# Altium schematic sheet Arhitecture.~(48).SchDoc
size A3; SheetNumber: 1; SheetTotal: 2
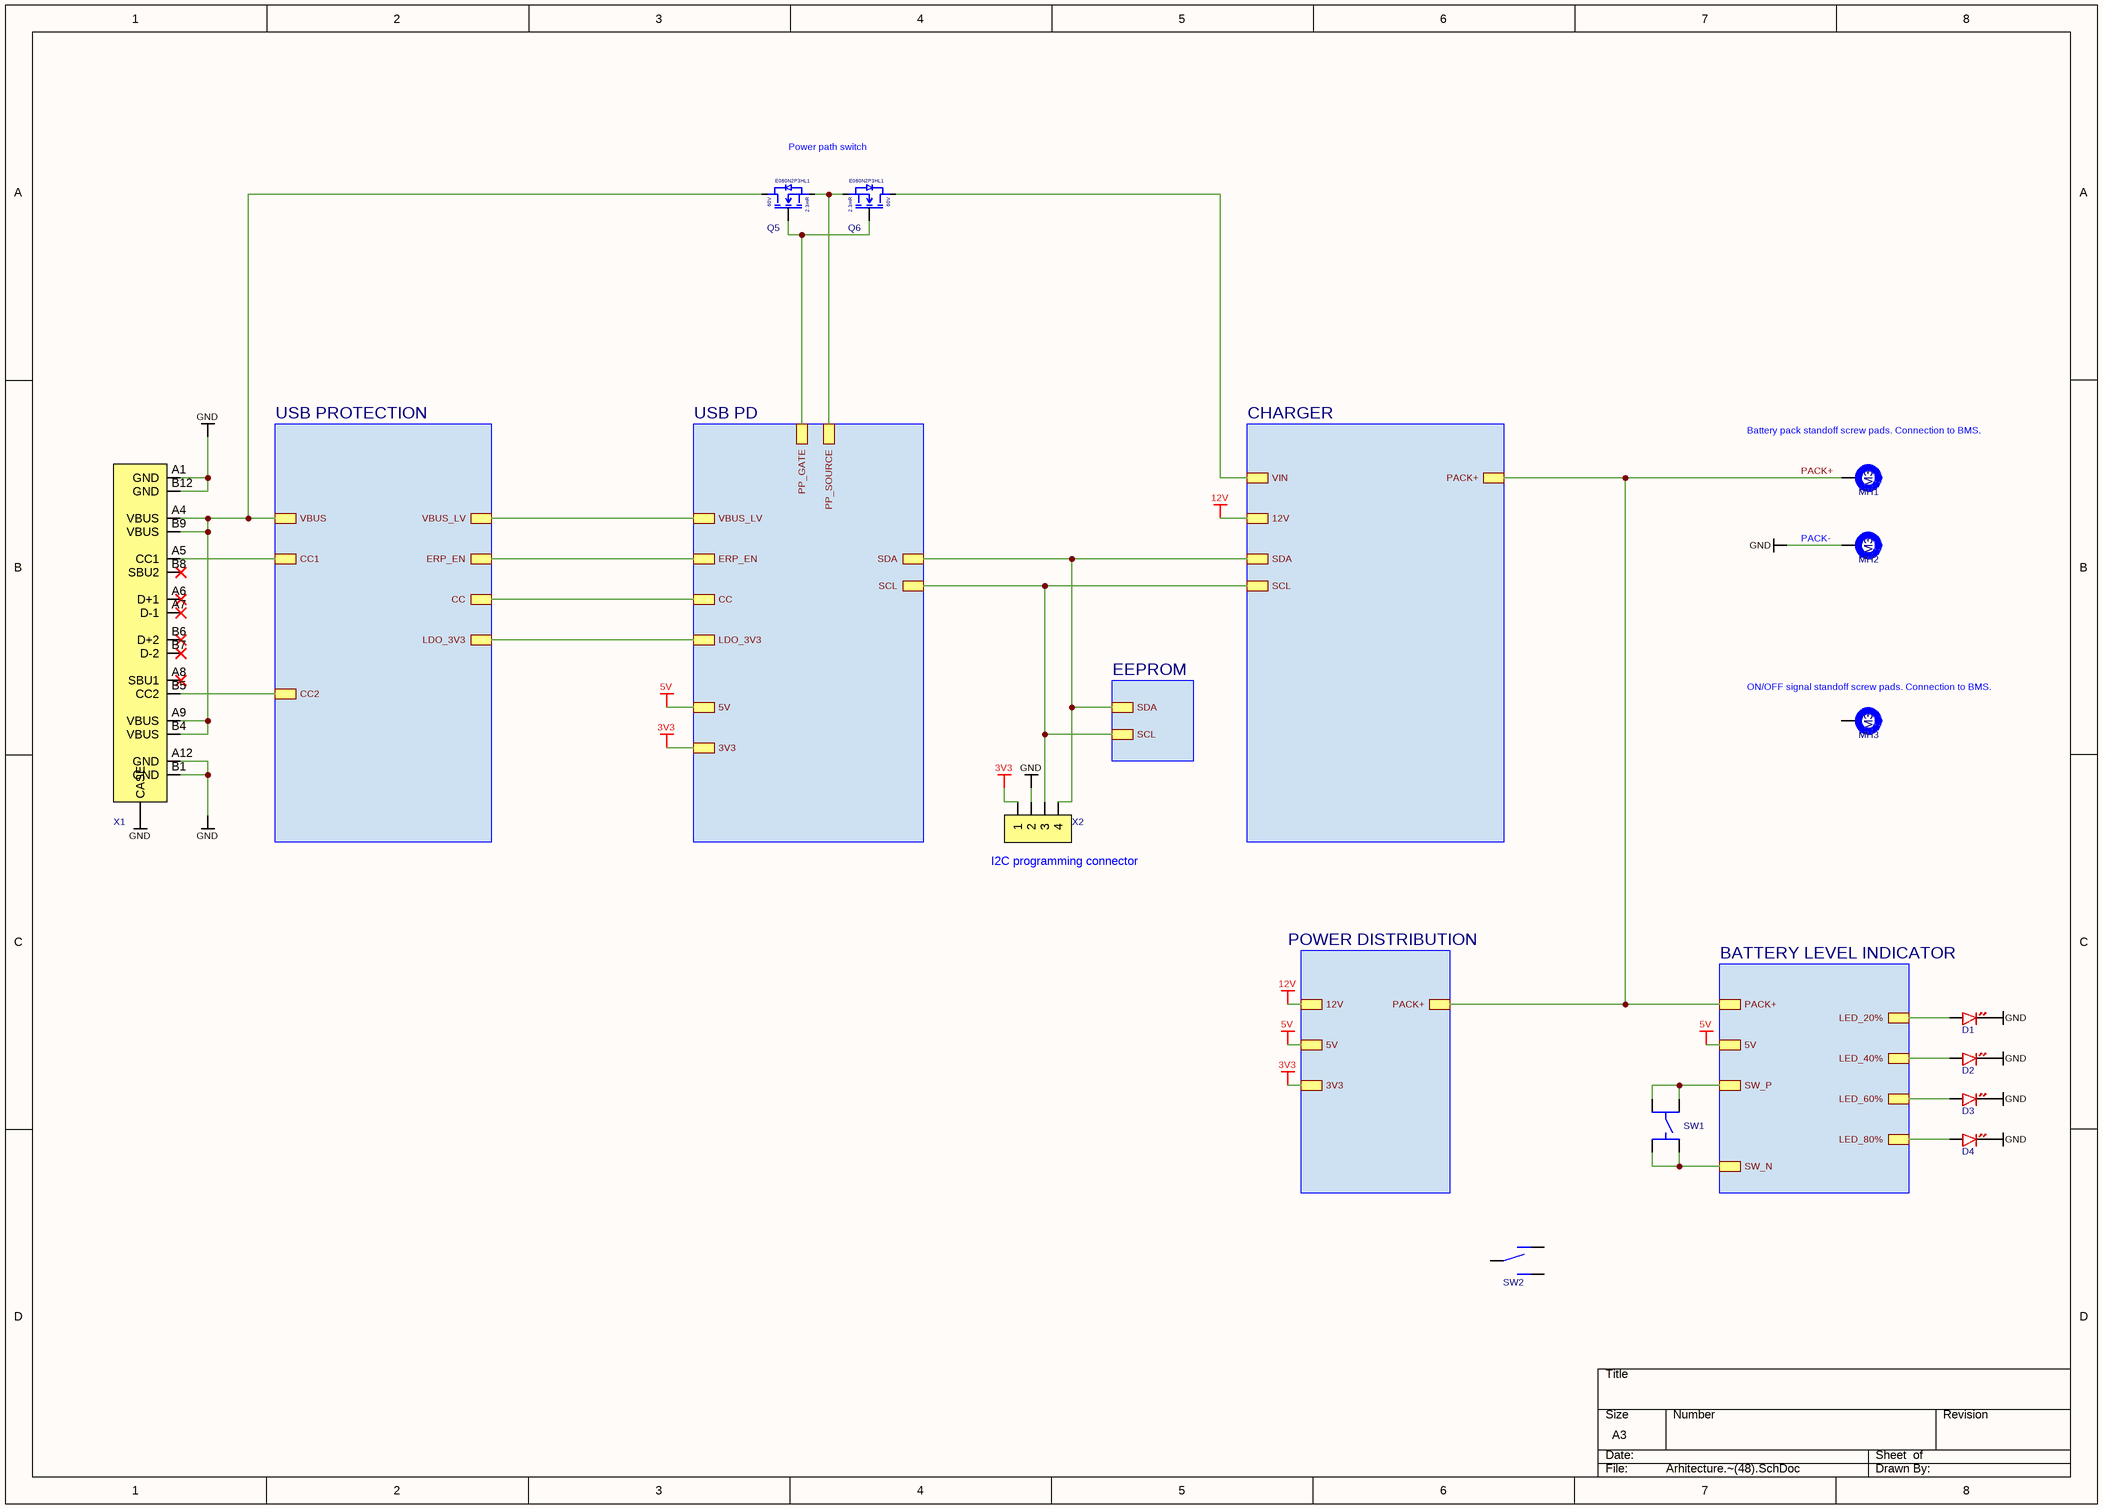
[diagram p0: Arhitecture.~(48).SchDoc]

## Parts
D1  XL-1608SURC-06  [DIODE_0603]  (value not drawn)
D2  XL-1608SURC-06  [DIODE_0603]  (value not drawn)
D3  XL-1608SURC-06  [DIODE_0603]  (value not drawn)
D4  XL-1608SURC-06  [DIODE_0603]  (value not drawn)
MH1  Hole size: M3  [M3 Plated]  (hidden comment: M?)  (no BOM)
MH2  Hole size: M3  [M3 Plated]  (hidden comment: M?)  (no BOM)
MH3  Hole size: M3  [M3 Plated]  (hidden comment: M?)  (no BOM)
Q5  Rds: 2.3mR  Voltage: 60V  [DFN-8 (5x6)]  (hidden comment: E060N2P3HL1)
Q6  Rds: 2.3mR  Voltage: 60V  [DFN-8 (5x6)]  (hidden comment: E060N2P3HL1)
SW1  TS4560TP  [TS4560TP]  (value not drawn)
SW2  SS-3235S-L3  [SS-3235S-L3]  (value not drawn)
X1  TYPE-C 16P LTH6.8  [TYPE-C 16P LTH6.8]  (value not drawn)
X2  B4B-PH-K-S(LF)(SN)  [B4B-PH-K-S(LF)(SN)]  (value not drawn)

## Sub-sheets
BATTERY LEVEL INDICATOR = Battery level indicator.SchDoc: PACK+, 5V, SW_N, SW_P, LED_20%, LED_40%, LED_60%, LED_80%
CHARGER = Charger.SchDoc: PACK+, VIN, SDA, SCL, 12V
EEPROM = EEPROM.SchDoc: SDA, SCL
POWER DISTRIBUTION = Power distribution.SchDoc: PACK+, 12V, 5V, 3V3
USB PD = USB PD.SchDoc: VBUS_LV, ERP_EN, CC, LDO_3V3, PP_GATE, PP_SOURCE, SDA, SCL, 5V, 3V3
USB PROTECTION = USB protection.SchDoc: VBUS, CC1, CC2, VBUS_LV, ERP_EN, CC, LDO_3V3

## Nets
3V3: X2.1 ; sheet POWER DISTRIBUTION/3V3, sheet USB PD/3V3
5V: sheet POWER DISTRIBUTION/5V, sheet USB PD/5V, sheet BATTERY LEVEL INDICATOR/5V
12V: sheet CHARGER/12V, sheet POWER DISTRIBUTION/12V
GND: D1.K D2.K D3.K D4.K MH2.1 X1.A1(GND) X1.A12(GND) X1.B1(GND) X1.B12(GND) X1.CASE X2.2
PACK+: MH1.1 ; sheet CHARGER/PACK+, sheet POWER DISTRIBUTION/PACK+, sheet BATTERY LEVEL INDICATOR/PACK+
NetD1_A: D1.A ; sheet BATTERY LEVEL INDICATOR/LED_20%
NetD2_A: D2.A ; sheet BATTERY LEVEL INDICATOR/LED_40%
NetD3_A: D3.A ; sheet BATTERY LEVEL INDICATOR/LED_60%
NetD4_A: D4.A ; sheet BATTERY LEVEL INDICATOR/LED_80%
NetQ5_D: Q5.D X1.A4(VBUS) X1.A9(VBUS) X1.B4(VBUS) X1.B9(VBUS) ; sheet USB PROTECTION/VBUS
NetQ5_G: Q5.G Q6.G ; sheet USB PD/PP_GATE
NetQ5_S: Q5.S Q6.S ; sheet USB PD/PP_SOURCE
NetQ6_D: Q6.D ; sheet CHARGER/VIN
NetSW1_1: SW1.1 SW1.2 ; sheet BATTERY LEVEL INDICATOR/SW_P
NetSW1_3: SW1.3 SW1.4 ; sheet BATTERY LEVEL INDICATOR/SW_N
NetX1_A5: X1.A5(CC1) ; sheet USB PROTECTION/CC1
NetX1_B5: X1.B5(CC2) ; sheet USB PROTECTION/CC2
NetX2_3: X2.3 ; sheet CHARGER/SCL, sheet EEPROM/SCL, sheet USB PD/SCL
NetX2_4: X2.4 ; sheet CHARGER/SDA, sheet EEPROM/SDA, sheet USB PD/SDA
(unnamed): sheet USB PD/VBUS_LV, sheet USB PROTECTION/VBUS_LV
(unnamed): sheet USB PD/ERP_EN, sheet USB PROTECTION/ERP_EN  [a separate net that carries the same name]
(unnamed): sheet USB PD/CC, sheet USB PROTECTION/CC  [a separate net that carries the same name]
(unnamed): sheet USB PD/LDO_3V3, sheet USB PROTECTION/LDO_3V3  [a separate net that carries the same name]

Not connected (* = marked no-connect by the designer): MH3 1; SW2 1 2 3; X1 A6(D+1)* A7(D-1)* A8(SBU1)* B6(D+2)* B7(D-2)* B8(SBU2)*

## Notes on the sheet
- Power path switch
- (near MH1) Battery pack standoff screw pads. Connection to BMS.
- (near MH2) PACK-
- (near MH3) ON/OFF signal standoff screw pads. Connection to BMS.
- (near X2) I2C programming connector

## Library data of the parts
D1-D4 = XL-1608SURC-06: LED Red 0603 25mA; Manufacturer: Xinglight
MH1-MH3 = Mounting hole: Generic mounting hole symbol
Q5 Q6 = E060N2P3HL1: Nmos 60V 180A 2.3mR PDFN5x6-8; Manufacturer: Existar
SW1 = TS4560TP: Switch Tactile SMD 4.5x4.5mm 6mmH SPST; Manufacturer: Shou Han
SW2 = SS-3235S-L3: Switch Slide SMD 9.1x3.5mm 6.6mmH; Manufacturer: XKB Connection
X1 = TYPE-C 16P LTH6.8: USB-C 16P SMD Vertical 6.50mmH; Manufacturer: Shou Han
X2 = B4B-PH-K-S(LF)(SN): Pin header 1x4 2.00mmP THT Vertical JST PH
